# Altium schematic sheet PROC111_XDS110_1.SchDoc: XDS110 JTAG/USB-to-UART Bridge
size 431 x 279 mm; Date: Not shown in title block; ApprovedBy: Not shown in title block; CheckedBy: Not shown in title block; Author: Not shown in title block; CompanyName: Not shown in title block; Engineer: Not shown in title block; Organization: Not shown in title block; Address1: Not shown in title block; Address2: Not shown in title block; Address3: Not shown in title block; Address4: Not shown in title block; DocumentNumber: 21; Revision: Use project parameter SCH_Rev; SheetNumber: 21; SheetTotal: 24; PageSetup: Record=PageOptions¦CenterHorizontal=True¦CenterVertical=True¦PrintScale=1.00¦XCorrection=1.00¦YCorrection=1.00¦PrintKind=0¦BorderSize=5000000¦LeftOffset=0¦BottomOffset=0¦Orientation=2¦PaperLength=1000¦PaperWidth=1000¦Scale=100¦PaperSource=15¦PrintQuality=600¦MediaType=1¦DitherType=10¦PaperKind=Letter¦PrintScaleMode=1
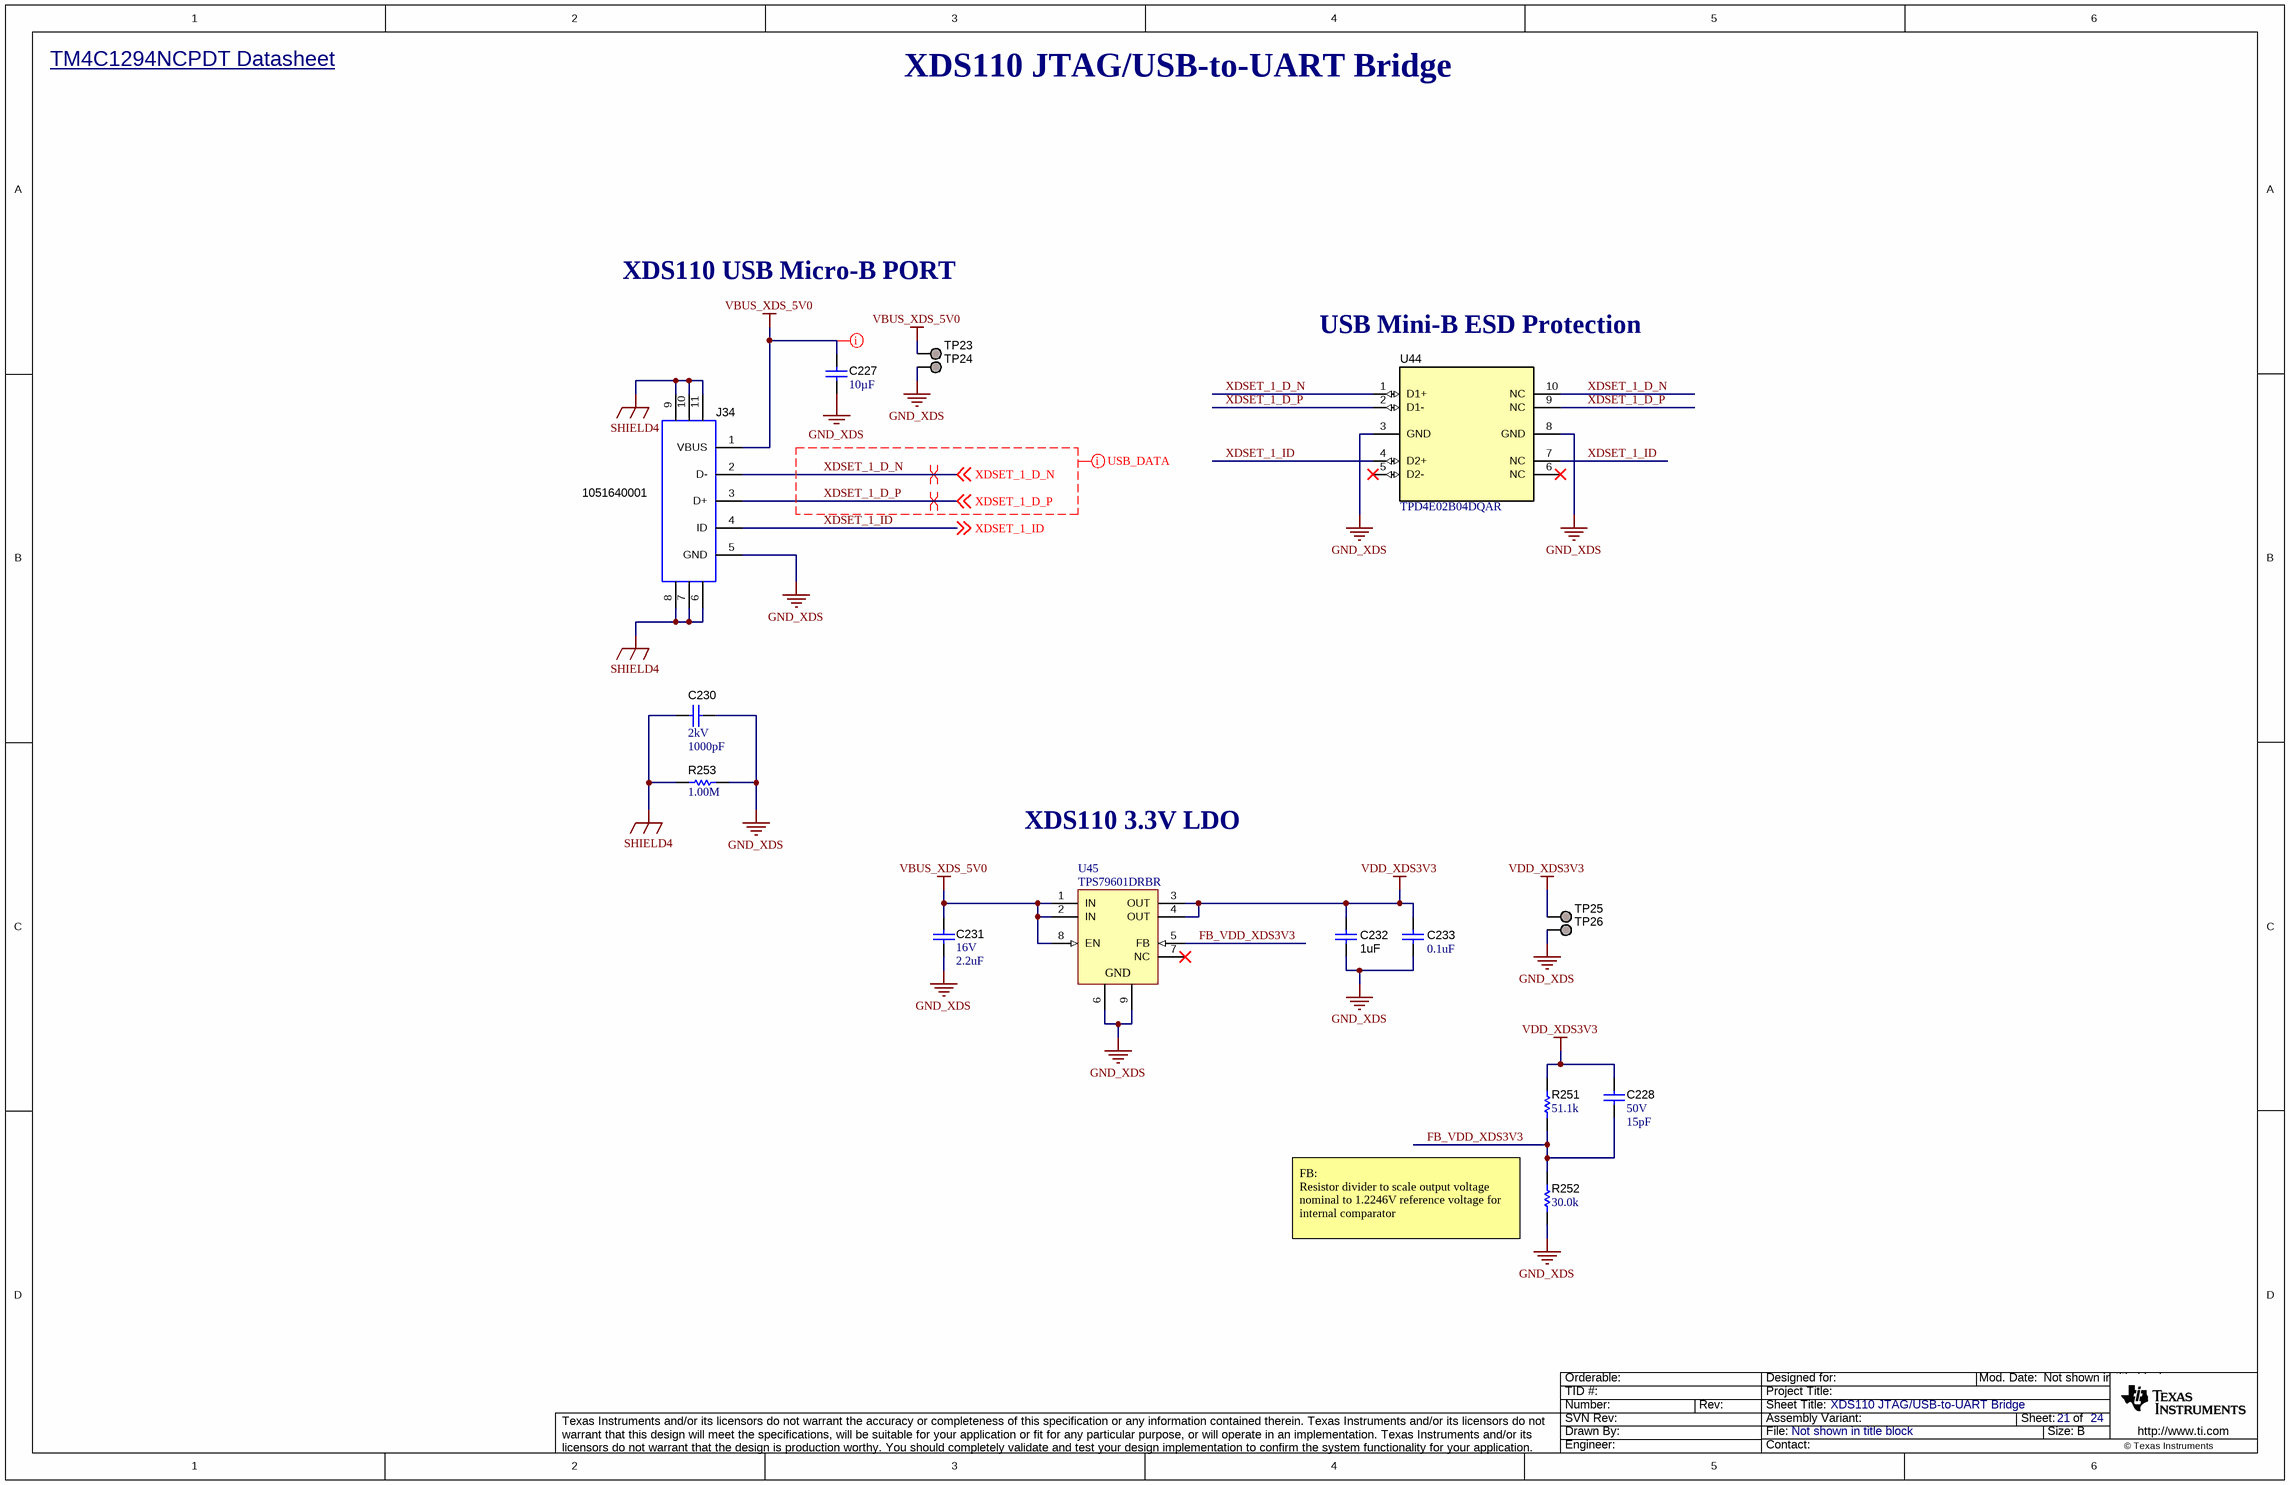
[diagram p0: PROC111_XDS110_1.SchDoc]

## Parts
C227  Cap_F: 10µF  [0805_HV]  (hidden comment: GRM21BZ71E106KE15L)
C228  VDC_V: 50V  ValueDisplayed: 15pF  [0402]  (hidden comment: GRM1555C1H150JA01D)
C230  VDC_V: 2kV  ValueDisplayed: 1000pF  [1808]  (hidden comment: GR442QR73D102KW01L)
C231  VDC_V: 16V  ValueDisplayed: 2.2uF  [0402]  (hidden comment: GRM155C81C225KE11D)
C232  ValueDisplayed: 1uF  [0402_070]  (hidden comment: GCM155C71A105KE38D)
C233  ValueDisplayed: 0.1uF  [0402]  (hidden comment: GRM155R71E104KE14D)
J34  1051640001  [Molex_1051640001]
R251  ValueDisplayed: 51.1k  [0402]  (hidden comment: CRCW040251K1FKED)
R252  ValueDisplayed: 30.0k  [0402]  (hidden comment: CRCW040230K0FKED)
R253  ValueDisplayed: 1.00M  [0805_HV]  (hidden comment: ERJ-6ENF1004V)
TP23  TESTPOINT  [TP_25MIL-SMT]  (value not drawn)  (no BOM)
TP24  TESTPOINT  [TP_25MIL-SMT]  (value not drawn)  (no BOM)
TP25  TESTPOINT  [TP_25MIL-SMT]  (value not drawn)  (no BOM)
TP26  TESTPOINT  [TP_25MIL-SMT]  (value not drawn)  (no BOM)
U44  TPD4E02B04DQAR  [DQA0010A]
U45  TPS79601DRBR  [DRB0008B]

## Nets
GND_XDS: C227.2 C230.1 C231.2 C232.2 C233.1 J34.5(GND) R252.1 R253.2 TP24.1 TP26.1 U44.3(GND) U44.8(GND) U45.6(GND) U45.9(GND)
SHIELD4: C230.2 J34.6 J34.7 J34.8 J34.9 J34.10 J34.11 R253.1
VBUS_XDS_5V0: C227.1 C231.1 J34.1(VBUS) TP23.1 U45.1(IN) U45.2(IN) U45.8(EN)
VDD_XDS3V3: C228.1 C232.1 C233.2 R251.2 TP25.1 U45.3(OUT) U45.4(OUT)
FB_VDD_XDS3V3: C228.2 R251.1 R252.2 U45.5(FB)
XDSET_1_D_N: J34.2(D-) U44.1(D1+) U44.10(NC) ; off-sheet XDSET_1_D_N
XDSET_1_D_P: J34.3(D+) U44.2(D1-) U44.9(NC) ; off-sheet XDSET_1_D_P
XDSET_1_ID: J34.4(ID) U44.4(D2+) U44.7(NC) ; off-sheet XDSET_1_ID

Not connected (* = marked no-connect by the designer): U44 5(D2-)* 6(NC)*; U45 7(NC)*

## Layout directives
differential pair: XDSET_1_D_N, XDSET_1_D_P
net class POWER: VBUS_XDS_5V0
mark named USB_DATA: XDSET_1_D_N, XDSET_1_D_P

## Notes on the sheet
- TM4C1294NCPDT Datasheet <http://www.ti.com/lit/ds/symlink/tm4c1294ncpdt.pdf>
- XDS110 JTAG/USB-to-UART Bridge
- XDS110 USB Micro-B PORT
- USB Mini-B ESD Protection
- XDS110 3.3V LDO
- (near R252) FB:
  Resistor divider to scale output voltage nominal to 1.2246V reference voltage for internal comparator

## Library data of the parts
C227 = CMP-0008378-2: CAP, CERM, 10 uF, 25 V, +/- 10%, X7R, 0805; Manufacturer: MuRata; TaMin_C: -55°C; Polarized: N; SizeAreaWB_mm2: 6.75; Value1: Unknown; U/M: EA; Value: 10uF; TaMax_C: 125°C; SizeZ_mm: 1.45; SizeX_mm: 2; SizeY_mm: 1.25; Cap_Case: 0805; Value2: 25V; SizeArea_mm2: 2.5; AEC Category: Q200
C228 = CMP-0006420-2: CAP, CERM, 15 pF, 50 V, +/- 5%, C0G/NP0, 0402; Manufacturer: MuRata; TaMin_C: -55°C; Polarized: N; SizeAreaWB_mm2: 3; Value1: Unknown; U/M: EA; Value: 15pF; TaMax_C: 125°C; SizeZ_mm: 0.6; SizeX_mm: 1; SizeY_mm: 0.5; AEC Category: Q200
C230 = CMP-0009436-2: CAP, CERM, 1000 pF, 2000 V, +/- 10%, X7R, 1808; Manufacturer: MuRata; TaMin_C: -55°C; Polarized: N; SizeAreaWB_mm2: 16.5; Value1: Unknown; U/M: EA; Value: 1000pF; TaMax_C: 125°C; SizeZ_mm: 2.03; SizeX_mm: 4.5; SizeY_mm: 2; Value2: 2000V; SizeArea_mm2: 9; Cap_F: 1nF; AEC Category: Q200
C231 = CMP-0006526-2: CAP, CERM, 2.2 uF, 16 V, +/- 10%, X6S, 0402; Manufacturer: MuRata; TaMin_C: -55°C; Polarized: N; SizeAreaWB_mm2: 3; Value1: Unknown; U/M: EA; Value: 2.2uF; TaMax_C: 105°C; SizeZ_mm: 0.6; SizeX_mm: 1; SizeY_mm: 0.5; Cap_F: 2.2µF; AEC Category: Q200
C232 = CMP-0006349-2: CAP, CERM, 1 uF, 10 V, +/- 10%, X7S, AEC-Q200 Grade 1, 0402; Manufacturer: MuRata; TaMin_C: -55°C; Polarized: N; SizeAreaWB_mm2: 3; Value1: Unknown; U/M: EA; Value: 1uF; TaMax_C: 125°C; SizeZ_mm: 0.7; SizeX_mm: 1; SizeY_mm: 0.5; Cap_Case: 0402; Value2: 10V; AEC Qualified: Y; Cap_F: 1µF; AEC Category: Q200
C233 = CMP-0006659-2: CAP, CERM, 0.1 uF, 25 V, +/- 10%, X7R, 0402; Manufacturer: MuRata; TaMin_C: -55°C; Polarized: N; SizeAreaWB_mm2: 3; U/M: EA; Value: 0.1uF; TaMax_C: 125°C; SizeZ_mm: 0.6; SizeX_mm: 1; SizeY_mm: 0.5; Value2: 25V; Cap_F: 100nF; AEC Category: Q200; Value1: Unknown
J34 = CMP-0055311-1: Receptacle, USB 2.0, Micro B, 5 Position, R/A, SMT; Manufacturer: Molex; CNHeader: FALSE; Current_A: 1.8A; Gender: Female; Voltage_V: 30V; Pitch_mm: 0.65; ContactFinish: Gold; CT: TRUE; Cert_UL: Y
R251 = CMP-0026437-2: RES, 51.1 k, 1%, 0.063 W, AEC-Q200 Grade 0, 0402; Manufacturer: Vishay-Dale; Power_W: 63mW; TempCo: 100 ppm/C; Value_Code: 51k1; Value: 51.1k; EIA_Code: E96; SizeX_mm: 1; SizeY_mm: 0.5; SizeZ_mm: 0.6; Value2: 0.063W; AEC Qualified: Y; VDC_V: 50V; AEC Category: Q200; AEC Grade: 0
R252 = CMP-0078244-2: RES, 30.0 k, 1%, 0.063 W, AEC-Q200 Grade 0, 0402; Manufacturer: Vishay-Dale; Power_W: 63mW; Green_Lifecycle: Active; TempCo: 100 ppm/C; Value_Code: 30k0; Green_REACh: Passed; Value: 30.0k; Res_ohm: 30k; SizeX_mm: 1; SizeY_mm: 0.5; SizeZ_mm: 0.6; Value2: 0.063W; AEC Qualified: Y; VDC_V: 50V; AEC Grade: 0; AEC Category: Q200
R253 = CMP-0021522-3: RES, 1.00 M, 1%, 0.125 W, AEC-Q200 Grade 0, 0805; Manufacturer: Panasonic; Power_W: 125mW; TempCo: 100 ppm/C; Value_Code: 1M00; Value: 1.00Meg; EIA_Code: E96; Res_ohm: 1M; SizeX_mm: 2; SizeY_mm: 1.25; SizeZ_mm: 1.45; Value2: 0.125W; SizeArea_mm2: 2.5; AEC Qualified: Y; AEC Category: Q200; AEC Grade: 0; SizeAreaWB_mm2: 6.75
TP23-TP26 = CMP-0078143-3: TEST POINT.  No entry in BOM.
U44 = CMP-0073612-3: 4-Channel ESD Protection Diode for USB Type-C and HDMI 2.0, DQA0010A (USON-10); Alternate Manufacturer: Texas Instruments; Green_Lifecycle: Active; SizeAreaWB_mm2: 7.0; Green_REACh: Passed; SizeZ_mm: 0.55; SizeX_mm: 1.0; SizeY_mm: 2.5; CompType: IC; AEC Category: Q200; AEC Qualified: Y
U45 = CMP-0036402-3: Single Output High PSRR LDO, 1 A, Adjustable 1.2 to 5.5 V Output, 2.7 to 5.5 V Input, 8-pin SON (DRB), -40 to 125 degC, Green (RoHS & no Sb/Br); Manufacturer: Texas Instruments; Vin(Min)(V): 2.7; Vout Adj(Max)(V): 5.5; Vout Adj(Min)(V): 1.2; Accuracy(%): 2; SubFamily: Single Channel LDO; Iq(Typ)(mA): 0.26; Vdo(Typ)(mV): 250; Iout(Max)(A): 1; AEC Category: Q200; AEC Qualified: N; CompType: IC; SizeAreaWB_mm2: 16.0; SizeArea_mm2: 9.0; SizeX_mm: 3.0; SizeZ_mm: 1.0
